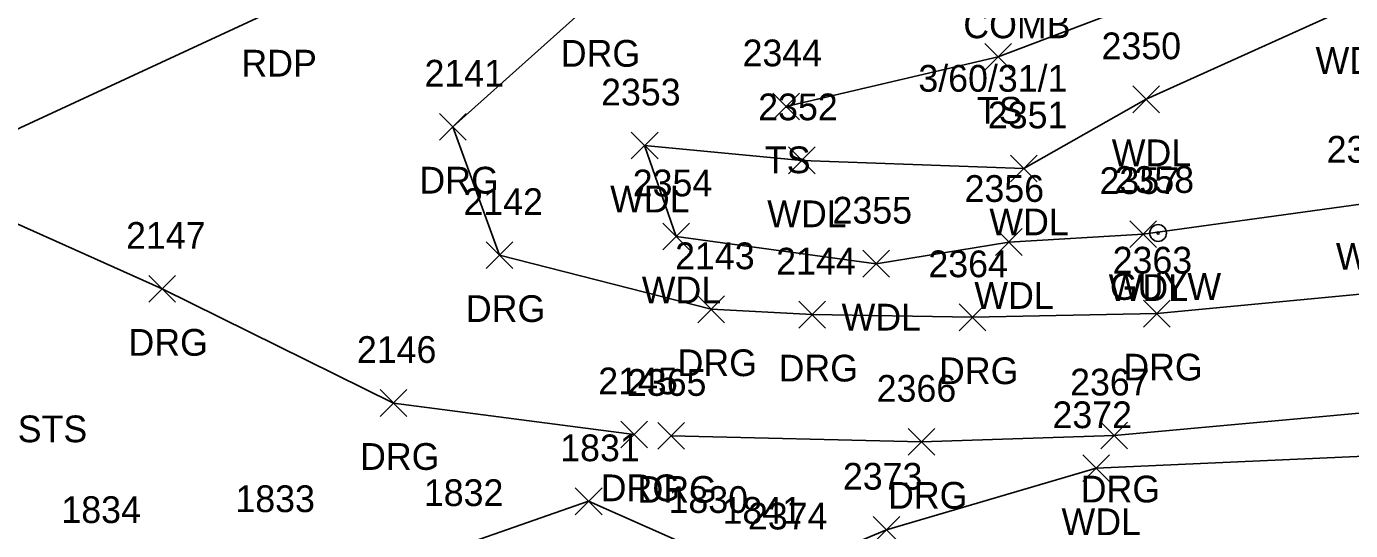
# Model space of a CAD drawing. Extents: x 1616726 to 1619875, y 273782 to 276557.
# Drawn here: x 1616995.8 to 1617094.9, y 276335.6 to 276373.3 of the extents above; entities that cross this region are included whole.
import ezdxf

# ---------------------------------------------------------------- set-up
doc = ezdxf.new("R2010")
doc.units = 0
for name, color, linetype in [('L_A', 7, 'Continuous'), ('L_I', 7, 'Continuous'), ('L_TIC', 7, 'Continuous'), ('LAWA', 7, 'Continuous'), ('LELB', 7, 'Continuous'), ('P_A', 7, 'Continuous'), ('PET', 7, 'Continuous'), ('R_A', 7, 'Continuous'), ('R_C', 7, 'Continuous'), ('R_I', 7, 'Continuous'), ('R_TIC', 7, 'Continuous'), ('RDG', 7, 'Continuous'), ('U_A', 7, 'Continuous'), ('U_C', 7, 'Continuous'), ('U_I', 7, 'Continuous'), ('UPGW', 7, 'Continuous')]:
    doc.layers.add(name, color=color, linetype=linetype)

msp = doc.modelspace()

# ---------------------------------------------------------------- linework, layer by layer
at = {"layer": 'L_TIC'}
for points in [[(1617067.52, 276370.013), (1617069.52, 276372.013)], [(1617069.52, 276370.013), (1617067.52, 276372.013)], [(1617078.602, 276366.832), (1617080.602, 276368.832)], [(1617080.602, 276366.832), (1617078.602, 276368.832)], [(1617051.654, 276366.305), (1617053.654, 276368.305)], [(1617053.654, 276366.305), (1617051.654, 276368.305)], [(1617041.067, 276363.373), (1617043.067, 276365.373)], [(1617043.067, 276363.373), (1617041.067, 276365.373)], [(1617052.824, 276362.266), (1617054.824, 276364.266)], [(1617054.824, 276362.266), (1617052.824, 276364.266)], [(1617069.443, 276361.661), (1617071.443, 276363.661)], [(1617071.443, 276361.661), (1617069.443, 276363.661)], [(1617078.371, 276356.751), (1617080.371, 276358.751)], [(1617080.371, 276356.751), (1617078.371, 276358.751)], [(1617043.436, 276356.577), (1617045.436, 276358.577)], [(1617045.436, 276356.577), (1617043.436, 276358.577)], [(1617068.321, 276356.159), (1617070.321, 276358.159)], [(1617070.321, 276356.159), (1617068.321, 276358.159)], [(1617058.388, 276354.538), (1617060.388, 276356.538)], [(1617060.388, 276354.538), (1617058.388, 276356.538)], [(1617074.845, 276339.233), (1617076.845, 276341.233)], [(1617076.845, 276339.233), (1617074.845, 276341.233)], [(1617036.877, 276336.76), (1617038.877, 276338.76)], [(1617038.877, 276336.76), (1617036.877, 276338.76)], [(1617059.163, 276334.633), (1617061.163, 276336.633)], [(1617061.163, 276334.633), (1617059.163, 276336.633)]]:
    msp.add_lwpolyline(points, dxfattribs=at)
at = {"layer": 'LAWA'}
for points in [[(1617113.036, 276383.542), (1617094.855, 276374.738), (1617079.602, 276367.832), (1617070.443, 276362.661), (1617053.824, 276363.266), (1617042.067, 276364.373), (1617044.436, 276357.577), (1617059.388, 276355.538), (1617069.321, 276357.159), (1617079.371, 276357.751), (1617096.373, 276360.095), (1617110.115, 276364.125)], [(1617131.584, 276346.038), (1617114.336, 276341.96), (1617075.845, 276340.233), (1617060.163, 276335.633), (1617053.06, 276332.653)]]:
    msp.add_lwpolyline(points, dxfattribs=at)
at = {"layer": 'LELB'}
for points in [[(1617052.654, 276367.305), (1617068.52, 276371.013), (1617088.759, 276378.682), (1617109.952, 276385.208)], [(1616978.199, 276327.348), (1616991.321, 276323.975), (1617002.989, 276326.908), (1617009.955, 276326.56), (1617017.916, 276322.159), (1617029.869, 276324.32), (1617039.92, 276328.912), (1617046.634, 276333.892), (1617037.877, 276337.76), (1617028.239, 276334.405), (1617014.137, 276333.953), (1617001.116, 276333.136)]]:
    msp.add_lwpolyline(points, dxfattribs=at)
at = {"layer": 'PET'}
msp.add_lwpolyline([(1617014.404, 276374.536), (1616987.83, 276362.226), (1616976.678, 276357.843), (1616969.871, 276350.951), (1616965.537, 276344.162), (1616964.241, 276339.945), (1616963.659, 276334.926), (1616964.456, 276330.122), (1616966.241, 276325.428), (1616953.454, 276321.458), (1616940.91, 276317.633), (1616926.659, 276333.645), (1616912.071, 276350.842), (1616900.384, 276364.101), (1616887.78, 276376.027)], dxfattribs=at)
at = {"layer": 'R_TIC'}
for points in [[(1617026.724, 276364.784), (1617028.724, 276366.784)], [(1617028.724, 276364.784), (1617026.724, 276366.784)], [(1617030.202, 276355.175), (1617032.202, 276357.175)], [(1617032.202, 276355.175), (1617030.202, 276357.175)], [(1617004.954, 276352.65), (1617006.954, 276354.65)], [(1617006.954, 276352.65), (1617004.954, 276354.65)], [(1617046.042, 276351.124), (1617048.042, 276353.124)], [(1617048.042, 276351.124), (1617046.042, 276353.124)], [(1617079.394, 276350.799), (1617081.394, 276352.799)], [(1617081.394, 276350.799), (1617079.394, 276352.799)], [(1617053.602, 276350.725), (1617055.602, 276352.725)], [(1617055.602, 276350.725), (1617053.602, 276352.725)], [(1617065.606, 276350.525), (1617067.606, 276352.525)], [(1617067.606, 276350.525), (1617065.606, 276352.525)], [(1617022.284, 276344.113), (1617024.284, 276346.113)], [(1617024.284, 276344.113), (1617022.284, 276346.113)], [(1617040.289, 276341.767), (1617042.289, 276343.767)], [(1617042.289, 276341.767), (1617040.289, 276343.767)], [(1617043.048, 276341.65), (1617045.048, 276343.65)], [(1617045.048, 276341.65), (1617043.048, 276343.65)], [(1617061.794, 276341.208), (1617063.794, 276343.208)], [(1617063.794, 276341.208), (1617061.794, 276343.208)], [(1617076.211, 276341.678), (1617078.211, 276343.678)], [(1617078.211, 276341.678), (1617076.211, 276343.678)]]:
    msp.add_lwpolyline(points, dxfattribs=at)
at = {"layer": 'RDG'}
for points in [[(1617077.026, 276406.734), (1617072.61, 276398.747), (1617072.537, 276395.537), (1617066.254, 276384.771), (1617038.304, 276375.271), (1617027.724, 276365.784), (1617031.202, 276356.175), (1617047.042, 276352.124), (1617054.602, 276351.725)], [(1617041.289, 276342.767), (1617023.284, 276345.113), (1617005.954, 276353.65), (1616988.347, 276361.528)], [(1617118.307, 276354.574), (1617101.883, 276353.865), (1617080.394, 276351.799), (1617066.606, 276351.525)], [(1617066.606, 276351.525), (1617054.602, 276351.725)], [(1617044.048, 276342.65), (1617062.794, 276342.208), (1617077.211, 276342.678), (1617110.314, 276345.704), (1617127.403, 276347.85), (1617127.537, 276347.893)]]:
    msp.add_lwpolyline(points, dxfattribs=at)
at = {"layer": 'UPGW'}
for radius in [0.625, 0.0833]:
    msp.add_circle((1617080.49, 276357.831), radius, dxfattribs=at)

# ---------------------------------------------------------------- texts
at = {"layer": 'L_A'}
for s, p in [('WDL', (1617092.272, 276369.738)), ('TS', (1617066.93, 276366.013)), ('WDL', (1617077.02, 276362.832)), ('TS', (1617051.064, 276362.305)), ('WDL', (1617039.485, 276359.373)), ('WDL', (1617051.241, 276358.266)), ('WDL', (1617067.861, 276357.661)), ('WDL', (1617093.79, 276355.095)), ('WDL', (1617041.854, 276352.577)), ('WDL', (1617066.739, 276352.159)), ('WDL', (1617076.788, 276352.751)), ('WDL', (1617056.805, 276350.538)), ('WDL', (1617073.262, 276335.233))]:
    msp.add_text(s, height=2, dxfattribs=at).set_placement(p)
at = {"layer": 'L_I'}
for s, p in [('2350', (1617076.256, 276370.832)), ('2344', (1617049.395, 276370.305)), ('2353', (1617038.807, 276367.373)), ('2352', (1617050.564, 276366.266)), ('2351', (1617067.751, 276365.661)), ('2359', (1617093.105, 276363.095)), ('2357', (1617076.111, 276360.751)), ('2354', (1617041.177, 276360.577)), ('2356', (1617066.006, 276360.159)), ('2355', (1617056.128, 276358.538)), ('2372', (1617072.585, 276343.233)), ('1831', (1617035.751, 276340.76)), ('2373', (1617056.903, 276338.633)), ('1833', (1617011.444, 276336.953)), ('1832', (1617025.546, 276337.405)), ('1834', (1616998.423, 276336.136)), ('1830', (1617043.855, 276336.892)), ('1841', (1617047.895, 276336.081)), ('2374', (1617049.8, 276335.653))]:
    msp.add_text(s, height=2, dxfattribs=at).set_placement(p)
at = {"layer": 'P_A'}
msp.add_text('RDP', height=2, dxfattribs=at).set_placement((1617011.893, 276369.536))
at = {"layer": 'R_A'}
for p in [(1617035.792, 276370.271), (1617025.212, 276360.784), (1617028.69, 276351.175), (1617003.442, 276348.65), (1617044.53, 276347.124), (1617052.09, 276346.725), (1617064.094, 276346.525), (1617077.883, 276346.799), (1617020.773, 276340.113), (1617038.777, 276337.767), (1617041.536, 276337.65), (1617060.283, 276337.208), (1617074.699, 276337.678)]:
    msp.add_text('DRG', height=2, dxfattribs=at).set_placement(p)
at = {"layer": 'R_C'}
msp.add_text('SGR W/ WOOD POSTS', height=2, dxfattribs=at).set_placement((1616971.382, 276342.179))
at = {"layer": 'R_I'}
for s, p in [('2141', (1617025.598, 276368.784)), ('2142', (1617028.509, 276359.175)), ('2147', (1617003.261, 276356.65)), ('2143', (1617044.349, 276355.124)), ('2363', (1617077.087, 276354.799)), ('2144', (1617051.909, 276354.725)), ('2364', (1617063.299, 276354.525)), ('2146', (1617020.536, 276348.113)), ('2145', (1617038.596, 276345.767)), ('2365', (1617040.741, 276345.65)), ('2366', (1617059.432, 276345.208)), ('2367', (1617073.904, 276345.678))]:
    msp.add_text(s, height=2, dxfattribs=at).set_placement(p)
at = {"layer": 'U_A'}
for s, p in [('COMB', (1617065.913, 276372.403)), ('GUYW', (1617076.884, 276352.831))]:
    msp.add_text(s, height=2, dxfattribs=at).set_placement(p)
at = {"layer": 'U_C'}
msp.add_text('3/60/31/1', height=2, dxfattribs=at).set_placement((1617062.551, 276368.403))
at = {"layer": 'U_I'}
msp.add_text('2358', height=2, dxfattribs=at).set_placement((1617077.23, 276360.831))

doc.saveas('drawing.dxf')
